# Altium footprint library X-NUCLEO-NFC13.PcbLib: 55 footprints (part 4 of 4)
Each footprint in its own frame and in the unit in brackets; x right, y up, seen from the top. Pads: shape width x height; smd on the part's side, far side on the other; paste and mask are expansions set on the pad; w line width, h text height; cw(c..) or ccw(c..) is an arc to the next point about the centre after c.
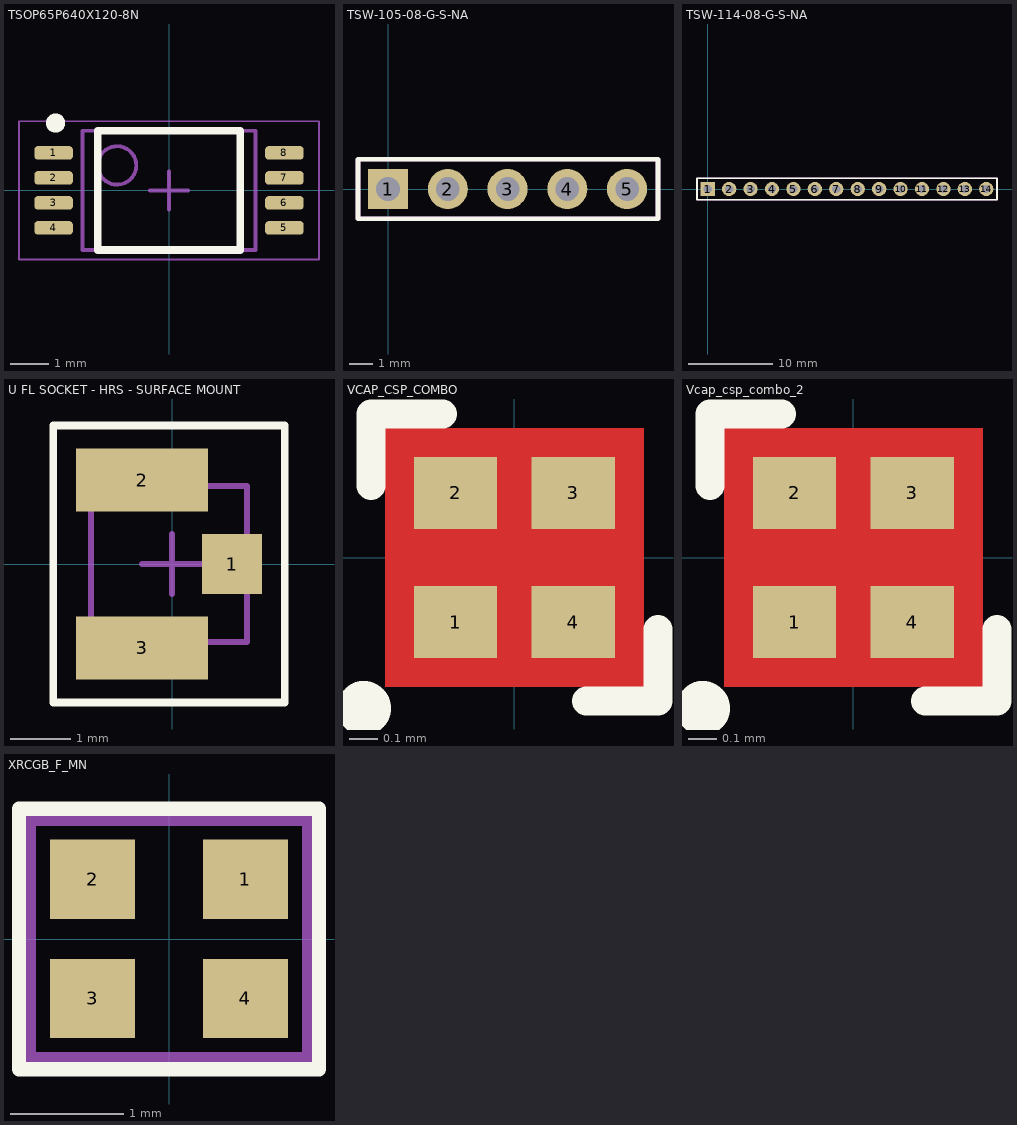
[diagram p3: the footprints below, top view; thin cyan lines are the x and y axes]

## TSOP65P640X120-8N [mm] "TSOP, 8-Leads, Body 3,00x4,40mm, Pitch 0,65mm, IPC Medium Density"
height 1.2
pads (8):
  rrect50% 1x0.35 smd: 1(-3,0.975) 2(-3,0.325) 3(-3,-0.325) 4(-3,-0.975) 5(3,-0.975) 6(3,-0.325) 7(3,0.325) 8(3,0.975)
Top Overlay:
  circle w0.25: c-2.95,1.75 r0.125
  lines w0.2: -1.85,-1.55 1.85,-1.55 1.85,1.55 -1.85,1.55 -1.85,-1.55
Top Assembly:
  circle w0.1: c-1.35,0.65 r0.5
  lines w0.1: -2.25,-1.55 2.25,-1.55 2.25,1.55 -2.25,1.55 -2.25,-1.55
Top Courtyard:
  lines w0.05: -3.9,-1.8 3.9,-1.8 3.9,1.8 -3.9,1.8 -3.9,-1.8
  lines w0.1: -0.5,0 0.5,0 ; 0,-0.5 0,0.5
3D body "TSOP65P640X120-8N.step": height 1.2, standoff 0, extent -3.2,-1.55 3.2,1.55

## TSW-105-08-G-S-NA [mm] "5 Pin header 90deg"
height 8
pads (5):
  rect 1.7x1.7 hole 1: 1(0,0)
  round 1.7 hole 1: 2(2.54,0) 3(5.08,0) 4(7.62,0) 5(10.16,0)
Top Overlay:
  lines w0.2: -1.275,-1.27 11.475,-1.27 11.475,1.27 -1.275,1.27 -1.275,-1.27
Top Assembly:
  lines w0.2: -1.275,-1.27 11.475,-1.27 11.475,1.27 -1.275,1.27 -1.275,-1.27
  text ".Designator" at 2.297,-2.076 h0.6
3D body "TSW-105-08-G-S-NA.stp": height 2.77, standoff -2.54, extent -1.25,-0.3 11.577,9.923

## TSW-114-08-G-S-NA [mm] "14 Pin header 90deg"
height 8
pads (14):
  rect 1.7x1.7 hole 1: 1(0,0)
  round 1.7 hole 1: 2(2.54,0) 3(5.08,0) 4(7.62,0) 5(10.16,0) 6(12.7,0) 7(15.24,0) 8(17.78,0) 9(20.32,0) 10(22.86,0) 11(25.4,0) 12(27.94,0) 13(30.48,0) 14(33.02,0)
Top Overlay:
  lines w0.2: -1.27,-1.27 -1.27,1.27 34.29,1.27 34.29,-1.27 -1.27,-1.27
Top Assembly:
  lines w0.2: -1.27,-1.27 -1.27,1.27 34.29,1.27 34.29,-1.27 -1.27,-1.27
  text ".Designator" at 13.797,-2.326 h0.6
3D body "TSW-114-08-G-S-NA.stp": height 2.77, standoff -2.54, extent -1.28,-0.316 34.407,9.907

## U FL SOCKET - HRS - SURFACE MOUNT [mm]
pads (3):
  rect 1x1 smd: 1(1,0)
  rect 2.2x1.05 smd: 2(-0.5,1.4) 3(-0.5,-1.4)
Top Overlay:
  lines w0.127: -1.978,-2.308 1.876,-2.308 1.876,2.308 -1.978,2.308 -1.978,-2.308
Top Assembly:
  lines w0.1: -1.35,-1.3 1.25,-1.3 1.25,1.3 -1.35,1.3 -1.35,-1.3
  text ".Designator" at -1.453,1.674 h0.6
Top Courtyard:
  lines w0.1: -0.5,0 0.5,0 ; 0,-0.5 0,0.5
3D body: height 1.25, standoff 0, extent -1.002,-0.998 0.991,0.998
3D body: height 1, standoff 0, extent -0.3,-0.299 0.298,0.299
3D body: height 1.26, standoff 0.66, extent -0.3,-0.297 0.3,0.299
3D body: height 0.35, standoff 0, extent -1.295,-1.27 1.219,1.27

## VCAP_CSP_COMBO [mm]
pads (4):
  rect 0.29x0.25 smd: 1(-0.205,-0.225) 2(-0.205,0.225) 3(0.205,0.225) 4(0.205,-0.225)
Top Layer:
  pour cut-out: -0.45,0.45 -0.45,-0.45 0.45,-0.45 0.45,0.45
Top Overlay:
  circle w0.15: c-0.525,-0.525 r0.02
  lines w0.1: -0.5,0.25 -0.5,0.5 -0.25,0.5 ; 0.25,-0.5 0.5,-0.5 0.5,-0.25
Top Assembly:
  region: -0.3,-0.05 0,-0.05 0,-0.3 -0.3,-0.3
  lines w0.15: -0.3,-0.3 -0.3,0.3 0.3,0.3 0.3,-0.3 -0.3,-0.3
  text ".Designator" at -0.75,0.75 h0.6
  text "GND" at -0.4,-0.45 h0.05
  text "BIAS" at -0.35,0.4 h0.05
  text "Port 1" at 0.3,-0.45 h0.05
  text "Port 2" at 0.25,0.4 h0.05
3D body: height 0.3, standoff 0.01, extent -0.3,-0.3 0.3,0.3

## Vcap_csp_combo_2 [mm]
pads (4):
  rect 0.29x0.25 smd: 1(-0.205,-0.225) 2(-0.205,0.225) 3(0.205,0.225) 4(0.205,-0.225)
Top Layer:
  pour cut-out: -0.45,0.45 -0.45,-0.45 0.45,-0.45 0.45,0.45
Top Overlay:
  circle w0.15: c-0.525,-0.525 r0.02
  lines w0.1: -0.5,0.25 -0.5,0.5 -0.25,0.5 ; 0.25,-0.5 0.5,-0.5 0.5,-0.25
Top Assembly:
  region: -0.3,-0.05 0,-0.05 0,-0.3 -0.3,-0.3
  lines w0.15: -0.3,-0.3 0.3,-0.3 0.3,0.3 -0.3,0.3 -0.3,-0.3
  text "Port 2" at 0.25,0.4 h0.05
  text "Port 1" at 0.3,-0.45 h0.05
  text "BIAS" at -0.35,0.4 h0.05
  text "GND" at -0.4,-0.45 h0.05
  text ".Designator" at -0.75,0.75 h0.6
3D body: height 0.3, standoff 0.01, extent -0.3,-0.3 0.3,0.3

## XRCGB_F_MN [mm]
pads (4):
  rect 0.75x0.7 smd mask+0.05: 1(0.675,0.527) 2(-0.675,0.527) 3(-0.675,-0.525) 4(0.675,-0.525)
Top Overlay:
  lines w0.127: -1.325,-1.15 1.325,-1.15 1.325,1.15 -1.325,1.15 -1.325,-1.15
Top Assembly:
  lines w0.1: -1.225,-1.05 1.225,-1.05 1.225,1.05 -1.225,1.05 -1.225,-1.05
  text ".Designator" at -1.75,1.45 h0.6
3D body: height 0.7, standoff 0, extent -1,-0.8 1,0.8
